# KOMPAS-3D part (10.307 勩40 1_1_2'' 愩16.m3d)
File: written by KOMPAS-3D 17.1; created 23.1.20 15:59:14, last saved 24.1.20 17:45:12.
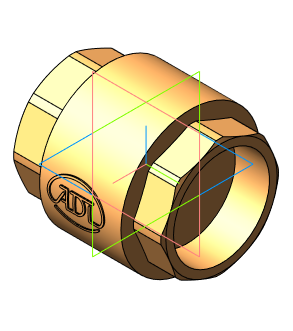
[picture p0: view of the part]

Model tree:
1. Операция без истории:2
